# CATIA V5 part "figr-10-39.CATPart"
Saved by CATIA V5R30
Part number: Part1
Bounding box of the stored display mesh (mm): x 0 to 56, y -58.044 to 12.863, z -44.68 to 88.822
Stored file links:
  D:\PROJECTS\CATIA V56R 2020\Resources\Parts File\c10_catia_v5_6r2020_prt\figr-10-39.CATPart
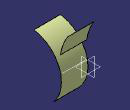
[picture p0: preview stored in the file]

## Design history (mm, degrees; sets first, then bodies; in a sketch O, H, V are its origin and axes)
Body1 (main body)
  Sketch1 on yz-plane, origin (0, 0, 0), H (0, 1, 0), V (0, 0, 1)
    arc A1 centre (-66.8734, 0) radius 66.8734 from (-58.0438, 66.2879) to (-17.1165, -44.68) cw
    coincidence: A1 O
    tangency: A1 V
  Extrude1: Element1 Sketch1, Lim1 56, Lim2 0
  Sketch2 on zx-plane, origin (0, 0, 0), H (-1, 0, 0), V (0, 0, 1)
    line L1 (-55.482, 13.9185) -> (0, 13.9185)
    point P1 (0, 13.9185)
    coincidence: P1 V
    horizontal: L1 H
  Project1: ToProject Sketch2, Support Extrude1
  Sweep1: type Circle, Guide Project1, Reference Extrude1, Radius 100, Angle1 20, Angle2 45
